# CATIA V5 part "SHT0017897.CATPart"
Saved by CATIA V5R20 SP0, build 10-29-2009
Part number: SHT0017897-20250319
Source: Unknown
Bounding box of the stored display mesh (mm): x -544.085 to 25.758, y -866.5 to -591.5, z 0.9 to 106.4
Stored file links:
  F:\福田A6\17-新能源车\数据\变更后数据\SHT0017897-主驾驶底部支架焊接总成-20250319 - 副本\SHT0017897-主驾驶底部支架焊接总成-20250319\SHT0017897.CATPart
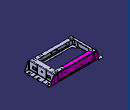
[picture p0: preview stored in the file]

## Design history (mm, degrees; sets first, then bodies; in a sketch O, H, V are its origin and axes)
Set1
  Point1 to Point4: stored without definition
Body1 "几何体" (main body)
Body2 "SHT0016014.1\\Q37108-焊接方螺母"
  Solid1: solid without history
Body3 "SHT0016014.1\\Q37108-焊接方螺母"
  Solid2: solid without history
Body4 "SHT0016014.1\\Q37108-焊接方螺母"
  Solid3: solid without history
Body5 "SHT0016014.1\\Q37108-焊接方螺母"
  Solid4: solid without history
Body6 "SHT0016014.1\\Q37108-焊接方螺母"
  Solid5: solid without history
Body7 "SHT0016014.1\\Q37108-焊接方螺母"
  Solid6: solid without history
Body8 "SHT0016014.1\\Q37106-焊接方螺母"
  Solid7: solid without history
Body9 "SHT0016014.1\\Q37110-焊接方螺母"
  Solid8: solid without history
Body10 "SHT0016014.1\\Q37110-焊接方螺母"
  Solid9: solid without history
Body11 "SHT0016014.1\\Q37106-焊接方螺母"
  Solid10: solid without history
Body12 "SHT0016014.1\\Q37106-焊接方螺母"
  Solid11: solid without history
Body13 "SHT0016014.1\\Q37106-焊接方螺母"
  Solid12: solid without history
Body14 "Q37108-焊接方螺母"
  Solid13: solid without history
Body15 "SHT0017890-主驾底支架前侧钣金"
  Solid14: solid without history
Body16 "SHT0017892-主驾底支架左侧钣金"
  Solid15: solid without history
Body17 "SHT0017891-主驾底支架后侧钣金"
  Solid16: solid without history
Body18 "SHT0017893-主驾底支架右侧钣金"
  Solid17: solid without history
Body19 "SHT0016151-支撑轴套"
  Solid18: solid without history
Body20 "SHT0016151-支撑轴套"
  Solid19: solid without history
Body21 "SHT0016151-支撑轴套"
  Solid20: solid without history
